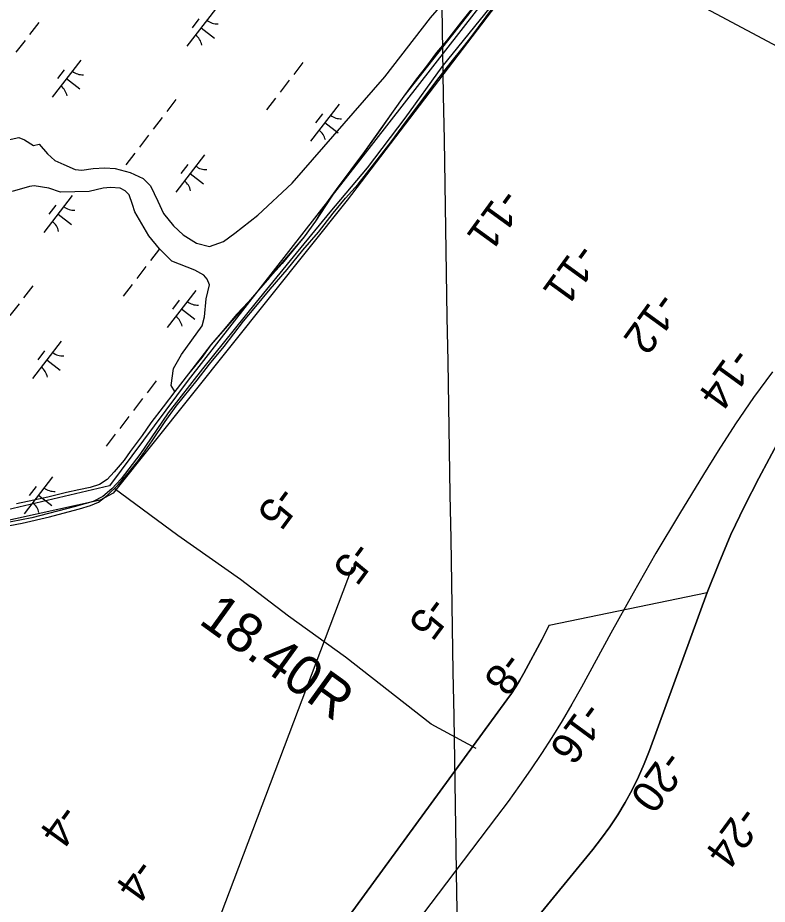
# Model space of a CAD drawing. Extents: x 3879599 to 3900814, y 146526 to 168888.
# Drawn here: x 3893542 to 3894343, y 160771 to 161718 of the extents above; entities that cross this region are included whole.
import ezdxf

# ---------------------------------------------------------------- set-up
doc = ezdxf.new("R2010")
doc.units = 0
for name, color, linetype in [('V-GRID-MAJR', 7, 'Continuous'), ('V-LEVE-TOET', 7, 'Continuous'), ('V-RIVR-EDGE', 7, 'Continuous'), ('V-RIVR-JETY', 7, 'Continuous'), ('V-RIVR-RANG', 7, 'Continuous'), ('V-RRAP-FSHR', 7, 'Continuous'), ('V-STRM-FMON', 7, 'Continuous'), ('V-TOPO-DPTH', 7, 'Continuous'), ('V-TOPO-MINR', 7, 'Continuous'), ('V-TOPO-SHOR', 7, 'Continuous'), ('V-WETL-SWMP', 7, 'Continuous')]:
    doc.layers.add(name, color=color, linetype=linetype)

msp = doc.modelspace()

# ---------------------------------------------------------------- linework, layer by layer
at = {"layer": 'V-GRID-MAJR'}
msp.add_spline([(3894134.72, 153416.68), (3894080.41, 156663.61), (3893979.03, 162723.86), (3893946.66, 164659.13)], degree=3, dxfattribs=at)
at = {"layer": 'V-LEVE-TOET'}
msp.add_lwpolyline([(3894032.05, 160937.68), (3893983.98, 160963.65), (3893892.36, 161035.24), (3893831.53, 161078.95), (3893780.32, 161118.19), (3893713.48, 161165.14), (3893645.62, 161215.22)], dxfattribs=at)
at = {"layer": 'V-RIVR-EDGE'}
msp.add_lwpolyline([(3894996.77, 162983.53), (3894972.23, 162947.83), (3894959.22, 162908.81), (3894952.72, 162865.13), (3894942.49, 162837.26), (3894932.27, 162822.39), (3894915.55, 162820.53), (3894892.32, 162812.17), (3894875.59, 162806.59), (3894862.58, 162797.3), (3894686.03, 162560.35), (3894502.98, 162313.18), (3894441.65, 162241.63), (3894369.17, 162130.13), (3894334.79, 162095.75), (3894315.28, 162075.3), (3893894.35, 161523.35), (3893644.39, 161210.21), (3893630.45, 161202.78), (3893449.25, 161162.82), (3893262.48, 161121.94), (3892618.54, 160989.06), (3892386.24, 160942.6)], dxfattribs=at)
at = {"layer": 'V-RIVR-JETY'}
for points in [[(3894047.03, 161729.5), (3893995.26, 161665.79), (3893955.69, 161610.93), (3893915.73, 161557.7), (3893875.8, 161510.53), (3893836.67, 161462.55), (3893797.14, 161414.17), (3893739.67, 161343.21), (3893702.97, 161296.03), (3893672.77, 161251.65), (3893652.79, 161225.44), (3893643.02, 161214.96), (3893633.26, 161206.91), (3893623.11, 161201.3), (3893602.83, 161195.74), (3893557.42, 161183.83), (3893490.94, 161171.22)], [(3894026.72, 161726.82), (3894015.2, 161712.75), (3894000.29, 161693.31), (3893989.79, 161680.91), (3893978.94, 161666.16), (3893968.44, 161652.76), (3893954.88, 161634.32), (3893941.66, 161615.88), (3893929.45, 161598.44), (3893914.19, 161576.99), (3893912.84, 161575.31), (3893882.33, 161534.75), (3893871.15, 161518.99), (3893860.28, 161500.88), (3893848.41, 161484.11), (3893836.56, 161469.71), (3893824.7, 161455.64), (3893811.16, 161440.56), (3893799.65, 161427.16), (3893788.81, 161414.77), (3893776.29, 161401.37), (3893761.73, 161383.95), (3893748.52, 161368.88), (3893739.03, 161355.13), (3893724.8, 161337.7), (3893710.23, 161318.93), (3893697.69, 161302.51), (3893684.48, 161285.42), (3893675.32, 161272.01), (3893662.44, 161254.91), (3893655.99, 161245.52), (3893645.5, 161233.12), (3893638.05, 161224.75), (3893629.94, 161219.41), (3893619.83, 161216.43), (3893607.7, 161213.8), (3893594.56, 161211.18), (3893574.68, 161205.9), (3893559.52, 161202.96), (3893541.32, 161199.01)]]:
    msp.add_lwpolyline(points, dxfattribs=at)
at = {"layer": 'V-RRAP-FSHR'}
msp.add_lwpolyline([(3894988.6, 162989.5), (3894928.15, 162903.5), (3894582.92, 162435.83), (3894412.91, 162213.52), (3894350.95, 162125.82), (3894296.72, 162068.74), (3894092.54, 161803.48), (3893724.45, 161331), (3893640.54, 161218.2), (3893416.13, 161165.56), (3892609.14, 161000)], dxfattribs=at)
at = {"layer": 'V-TOPO-DPTH'}
for points in [[(3894583.39, 161564.9), (3894255.7, 161739.59), (3894330.09, 161816.04), (3894779.1, 162471.69), (3894959.67, 162614.35), (3894982.55, 162633.86), (3895004.38, 162654.41), (3895024.63, 162676.51), (3895043.83, 162699.66), (3895072.99, 162737.61), (3895076.66, 162742.66), (3895080.14, 162747.83), (3895083.35, 162753.17), (3895086.37, 162758.63), (3895101.79, 162788.37), (3895104.27, 162794.7), (3895105.86, 162801.16), (3895106.1, 162807.8), (3895105.44, 162814.57), (3895407.09, 162684.23)], [(3893985.21, 160620.7), (3894156.42, 160829.61), (3894165.85, 160841.71), (3894174.87, 160854.1), (3894183.27, 160866.91), (3894191.25, 160880.01), (3894198.57, 160893.49), (3894205.4, 160907.19), (3894211.52, 160921.23), (3894217.16, 160935.5), (3894278.79, 161104.11), (3894290.98, 161135.36), (3894304.04, 161166.23), (3894318.41, 161196.5), (3894333.64, 161226.39), (3894355.85, 161267.74)], [(3893486.9, 160314.42), (3893580.4, 160363.17), (3893819.18, 160655.32), (3893821.65, 160658.36), (3893824.11, 160661.42), (3893826.55, 160664.49), (3893828.97, 160667.57), (3893831.5, 160670.81), (3893833.8, 160673.76), (3893834.94, 160675.24), (3893836.07, 160676.72), (3893839.68, 160681.45), (3893842.6, 160685.31), (3893845.51, 160689.18), (3893848.4, 160693.07), (3893851.26, 160696.97), (3894064.74, 160989.45), (3894069.57, 160996.36), (3894074.22, 161003.39), (3894078.59, 161010.59), (3894082.78, 161017.92), (3894102.62, 161054.34), (3894109.88, 161069.43), (3894278.79, 161104.11)], [(3894278.79, 161104.11), (3894217.16, 160935.5), (3894211.52, 160921.23), (3894205.4, 160907.19), (3894198.57, 160893.49), (3894191.25, 160880.01), (3894183.27, 160866.91), (3894174.87, 160854.1), (3894165.85, 160841.71), (3894156.42, 160829.61), (3893985.21, 160620.7)]]:
    msp.add_lwpolyline(points, dxfattribs=at)
at = {"layer": 'V-TOPO-MINR'}
for points in [[(3894348.48, 161339.93), (3894328.12, 161312.5), (3894308.84, 161284.3), (3894290.27, 161255.6), (3894274.58, 161230.31), (3894249.06, 161188.37), (3894224.01, 161146.16), (3894199.67, 161103.53), (3894175.81, 161060.63), (3894144.39, 161003.02), (3894134.23, 160984.97), (3894123.77, 160967.1), (3894112.84, 160949.51), (3894101.61, 160932.11), (3894089.98, 160914.96), (3894078.15, 160897.96), (3894066.01, 160881.18), (3894053.66, 160864.54), (3893921.38, 160689.67)], [(3894355.85, 161267.74), (3894333.64, 161226.39), (3894318.41, 161196.5), (3894304.04, 161166.23), (3894290.98, 161135.36), (3894278.79, 161104.11), (3894217.16, 160935.5), (3894211.52, 160921.23), (3894205.4, 160907.19), (3894198.57, 160893.49), (3894191.25, 160880.01), (3894183.27, 160866.91), (3894174.87, 160854.1), (3894165.85, 160841.71), (3894156.42, 160829.61), (3893985.21, 160620.7)], [(3893899.62, 161131.12), (3893749.51, 160734.21), (3893499.23, 160421.58)], [(3894109.88, 161069.43), (3894102.62, 161054.34), (3894082.78, 161017.92), (3894078.59, 161010.59), (3894074.22, 161003.39), (3894069.57, 160996.36), (3894064.74, 160989.45), (3893851.26, 160696.97), (3893848.4, 160693.07), (3893845.51, 160689.18), (3893842.6, 160685.31), (3893839.68, 160681.45), (3893836.07, 160676.72), (3893834.94, 160675.24), (3893833.8, 160673.76), (3893831.5, 160670.81), (3893828.97, 160667.57), (3893826.55, 160664.49), (3893824.11, 160661.42), (3893821.65, 160658.36), (3893819.18, 160655.32), (3893580.4, 160363.17), (3893486.9, 160314.42)]]:
    msp.add_lwpolyline(points, dxfattribs=at)
at = {"layer": 'V-TOPO-SHOR'}
for points in [[(3893532.14, 161587.57), (3893543.51, 161590.2), (3893549.63, 161587.57), (3893559.25, 161581.45), (3893565.37, 161583.2), (3893574.12, 161572.71), (3893581.99, 161565.71), (3893591.6, 161561.34), (3893603.85, 161556.09), (3893610.84, 161555.22), (3893623.08, 161556.97), (3893635.33, 161557.84), (3893646.69, 161556.97), (3893662.44, 161552.59), (3893676.43, 161546.47), (3893684.3, 161538.6), (3893692.17, 161521.99), (3893698.29, 161508.87), (3893708.78, 161495.75), (3893719.27, 161486.14), (3893733.27, 161477.39), (3893747.26, 161473.89), (3893762.12, 161479.14), (3893774.37, 161487.88), (3893798.85, 161507.12), (3893835.58, 161541.23), (3893934.39, 161654.91), (3893983.36, 161717.87), (3894022.71, 161763.34)], [(3894037.22, 161739.22), (3893954.88, 161634.32), (3893912.84, 161575.31), (3893882.33, 161534.75), (3893860.28, 161500.88), (3893848.41, 161484.11), (3893788.81, 161414.77), (3893748.52, 161368.88), (3893724.8, 161337.7), (3893710.23, 161318.93), (3893706.16, 161325.24), (3893708.78, 161343.6), (3893717.53, 161358.47), (3893739.39, 161389.07), (3893742.01, 161398.69), (3893743.76, 161417.93), (3893747.26, 161432.79), (3893744.63, 161438.92), (3893741.14, 161443.29), (3893731.52, 161448.53), (3893707.03, 161458.15), (3893693.92, 161471.27), (3893682.55, 161485.26), (3893667.68, 161510.62), (3893665.06, 161518.49), (3893661.56, 161528.98), (3893657.19, 161533.36), (3893651.94, 161535.98), (3893641.45, 161536.85), (3893633.58, 161535.98), (3893618.71, 161532.48), (3893588.11, 161531.61), (3893575.86, 161535.98), (3893560.12, 161538.6), (3893554.88, 161537.73), (3893536.51, 161532.48)]]:
    msp.add_lwpolyline(points, dxfattribs=at)
at = {"layer": 'V-WETL-SWMP'}
for p, q in [((3894026.2, 161696.95), (3894075.56, 161763.35)), ((3893753.69, 161727.19), (3893723.23, 161687.54)), ((3893736, 161716.83), (3893728.69, 161707.31)), ((3893564.96, 161712.94), (3893555.21, 161700.26)), ((3893738.46, 161707.37), (3893752.73, 161696.4)), ((3894018.45, 161686.86), (3894026.2, 161696.95)), ((3893550.34, 161693.91), (3893540.59, 161681.23)), ((3894005.41, 161670.73), (3894018.45, 161686.86)), ((3893609.87, 161672.86), (3893579.41, 161633.21)), ((3893846.95, 161670.28), (3893837.2, 161657.6)), ((3893989.91, 161650.96), (3894005.41, 161670.73)), ((3893592.18, 161662.49), (3893584.86, 161652.98)), ((3893594.64, 161653.03), (3893608.91, 161642.06)), ((3893832.33, 161651.25), (3893822.58, 161638.57)), ((3893974.41, 161629.99), (3893989.91, 161650.96)), ((3893711.48, 161630.62), (3893701.73, 161617.93)), ((3893817.71, 161632.22), (3893807.96, 161619.54)), ((3893956.87, 161606.99), (3893974.41, 161629.99)), ((3893885.59, 161625.84), (3893855.12, 161586.19)), ((3893696.85, 161611.59), (3893687.11, 161598.9)), ((3893867.89, 161615.47), (3893860.58, 161605.96)), ((3893870.35, 161606.01), (3893884.62, 161595.04)), ((3893941.36, 161585.61), (3893956.87, 161606.99)), ((3893682.23, 161592.56), (3893672.48, 161579.87)), ((3893921.38, 161559.79), (3893941.36, 161585.61)), ((3893667.61, 161573.53), (3893657.86, 161560.84)), ((3893741.76, 161571.5), (3893711.3, 161531.86)), ((3893724.07, 161561.14), (3893716.76, 161551.62)), ((3893905.89, 161540.43), (3893921.38, 161559.79)), ((3893726.53, 161551.68), (3893740.8, 161540.71)), ((3893892.44, 161525.51), (3893905.89, 161540.43)), ((3893600.78, 161528.2), (3893570.31, 161488.56)), ((3893879.39, 161509.38), (3893892.44, 161525.51)), ((3893583.08, 161517.84), (3893575.77, 161508.33)), ((3893585.55, 161508.38), (3893599.82, 161497.41)), ((3893863.49, 161489.21), (3893879.39, 161509.38)), ((3893846.78, 161469.86), (3893863.49, 161489.21)), ((3893694.04, 161471.3), (3893684.29, 161458.61)), ((3893830.06, 161449.29), (3893846.78, 161469.86)), ((3893679.41, 161452.27), (3893669.67, 161439.58)), ((3893812.13, 161428.33), (3893830.06, 161449.29)), ((3893558.56, 161431.63), (3893548.81, 161418.95)), ((3893664.79, 161433.24), (3893655.04, 161420.55)), ((3893732.67, 161426.85), (3893702.2, 161387.2)), ((3893796.64, 161409.78), (3893812.13, 161428.33)), ((3893543.94, 161412.6), (3893534.19, 161399.92)), ((3893714.98, 161416.49), (3893707.66, 161406.97)), ((3893717.44, 161407.03), (3893731.71, 161396.06)), ((3893783.6, 161394.05), (3893796.64, 161409.78)), ((3893762.8, 161367.02), (3893783.6, 161394.05)), ((3893588.85, 161372.52), (3893558.38, 161332.87)), ((3893747.31, 161348.07), (3893762.8, 161367.02)), ((3893571.15, 161362.15), (3893563.84, 161352.64)), ((3893573.62, 161352.69), (3893587.89, 161341.72)), ((3893734.25, 161331.13), (3893747.31, 161348.07)), ((3893690.46, 161330.28), (3893680.71, 161317.59)), ((3893711.83, 161303.3), (3893734.25, 161331.13)), ((3893675.83, 161311.25), (3893666.08, 161298.56)), ((3893700, 161286.75), (3893711.83, 161303.3)), ((3893661.21, 161292.22), (3893651.46, 161279.53)), ((3893686.12, 161266.17), (3893700, 161286.75)), ((3893646.58, 161273.19), (3893636.83, 161260.5)), ((3893671.02, 161244.78), (3893686.12, 161266.17)), ((3893658.79, 161229.46), (3893671.02, 161244.78)), ((3893579.76, 161227.87), (3893549.29, 161188.22)), ((3893649.82, 161219.38), (3893658.79, 161229.46)), ((3893562.06, 161217.5), (3893554.75, 161207.99)), ((3893638.42, 161208.1), (3893649.82, 161219.38)), ((3893564.52, 161208.04), (3893578.8, 161197.07)), ((3893628.66, 161200.86), (3893638.42, 161208.1)), ((3893590.93, 161188.91), (3893608.37, 161193.68)), ((3893608.37, 161193.68), (3893620.14, 161197.26)), ((3893620.14, 161197.26), (3893628.66, 161200.86)), ((3893547.13, 161178.21), (3893576.33, 161184.94)), ((3893576.33, 161184.94), (3893590.93, 161188.91)), ((3893457.12, 161161.67), (3893547.13, 161178.21))]:
    msp.add_line(p, q, dxfattribs=at)
for points in [[(3893532.14, 161587.57), (3893543.51, 161590.2), (3893549.63, 161587.57), (3893559.25, 161581.45), (3893565.37, 161583.2), (3893574.12, 161572.71), (3893581.99, 161565.71), (3893591.6, 161561.34), (3893603.85, 161556.09), (3893610.84, 161555.22), (3893623.08, 161556.97), (3893635.33, 161557.84), (3893646.69, 161556.97), (3893662.44, 161552.59), (3893676.43, 161546.47), (3893684.3, 161538.6), (3893692.17, 161521.99), (3893698.29, 161508.87), (3893708.78, 161495.75), (3893719.27, 161486.14), (3893733.27, 161477.39), (3893747.26, 161473.89), (3893762.12, 161479.14), (3893774.37, 161487.88), (3893798.85, 161507.12), (3893835.58, 161541.23), (3893934.39, 161654.91), (3893983.36, 161717.87), (3894022.71, 161763.34)], [(3894037.22, 161739.22), (3893954.88, 161634.32), (3893912.84, 161575.31), (3893882.33, 161534.75), (3893860.28, 161500.88), (3893848.41, 161484.11), (3893788.81, 161414.77), (3893748.52, 161368.88), (3893724.8, 161337.7), (3893710.23, 161318.93), (3893706.16, 161325.24), (3893708.78, 161343.6), (3893717.53, 161358.47), (3893739.39, 161389.07), (3893742.01, 161398.69), (3893743.76, 161417.93), (3893747.26, 161432.79), (3893744.63, 161438.92), (3893741.14, 161443.29), (3893731.52, 161448.53), (3893707.03, 161458.15), (3893693.92, 161471.27), (3893682.55, 161485.26), (3893667.68, 161510.62), (3893665.06, 161518.49), (3893661.56, 161528.98), (3893657.19, 161533.36), (3893651.94, 161535.98), (3893641.45, 161536.85), (3893633.58, 161535.98), (3893618.71, 161532.48), (3893588.11, 161531.61), (3893575.86, 161535.98), (3893560.12, 161538.6), (3893554.88, 161537.73), (3893536.51, 161532.48)]]:
    msp.add_lwpolyline(points, dxfattribs=at)
for centre, start, end in [((3893755.48, 161729.12), 231.68688, 273.23054), ((3893721.82, 161685.32), 11.68688, 53.23054), ((3893611.66, 161674.79), 231.68688, 273.23054), ((3893578, 161630.99), 11.68688, 53.23054), ((3893887.37, 161627.77), 231.68688, 273.23054), ((3893853.71, 161583.97), 11.68688, 53.23054), ((3893743.55, 161573.43), 231.68688, 273.23054), ((3893709.89, 161529.63), 11.68688, 53.23054), ((3893602.57, 161530.14), 231.68688, 273.23054), ((3893568.9, 161486.34), 11.68688, 53.23054), ((3893734.46, 161428.78), 231.68688, 273.23054), ((3893700.8, 161384.98), 11.68688, 53.23054), ((3893590.63, 161374.45), 231.68688, 273.23054), ((3893556.97, 161330.65), 11.68688, 53.23054), ((3893581.54, 161229.8), 231.68688, 273.23054), ((3893547.88, 161186), 11.68688, 53.23054)]:
    msp.add_arc(centre, 17.62, start, end, dxfattribs=at)

# ---------------------------------------------------------------- texts
at = {"layer": 'V-RIVR-RANG'}
for s, rotation, p in [('-11', 234.05833, (3894058.73, 161538.06)), ('-11', 234.05833, (3894139.84, 161479.56)), ('-12', 234.05833, (3894225.82, 161427.79)), ('-14', 234.05833, (3894306.07, 161368.12)), ('-5', 233.67833, (3893820.48, 161220.58)), ('-5', 233.67833, (3893901.2, 161161.55)), ('-5', 233.67833, (3893981.92, 161102.52)), ('-8', 233.67833, (3894062.33, 161043.07)), ('-16', 233.67833, (3894147.42, 160989.99)), ('-20', 233.67833, (3894233.38, 160938.08)), ('-4', 234.20833, (3893587.74, 160880.46)), ('-24', 233.67833, (3894313.78, 160878.63)), ('-4', 234.20833, (3893669.01, 160822.18))]:
    msp.add_text(s, height=33.5, rotation=rotation, dxfattribs=at).set_placement(p)
at = {"layer": 'V-STRM-FMON'}
msp.add_text('18.40R', height=42, rotation=324.17001, dxfattribs=at).set_placement((3893734.53, 161071.96))

doc.saveas('drawing.dxf')
